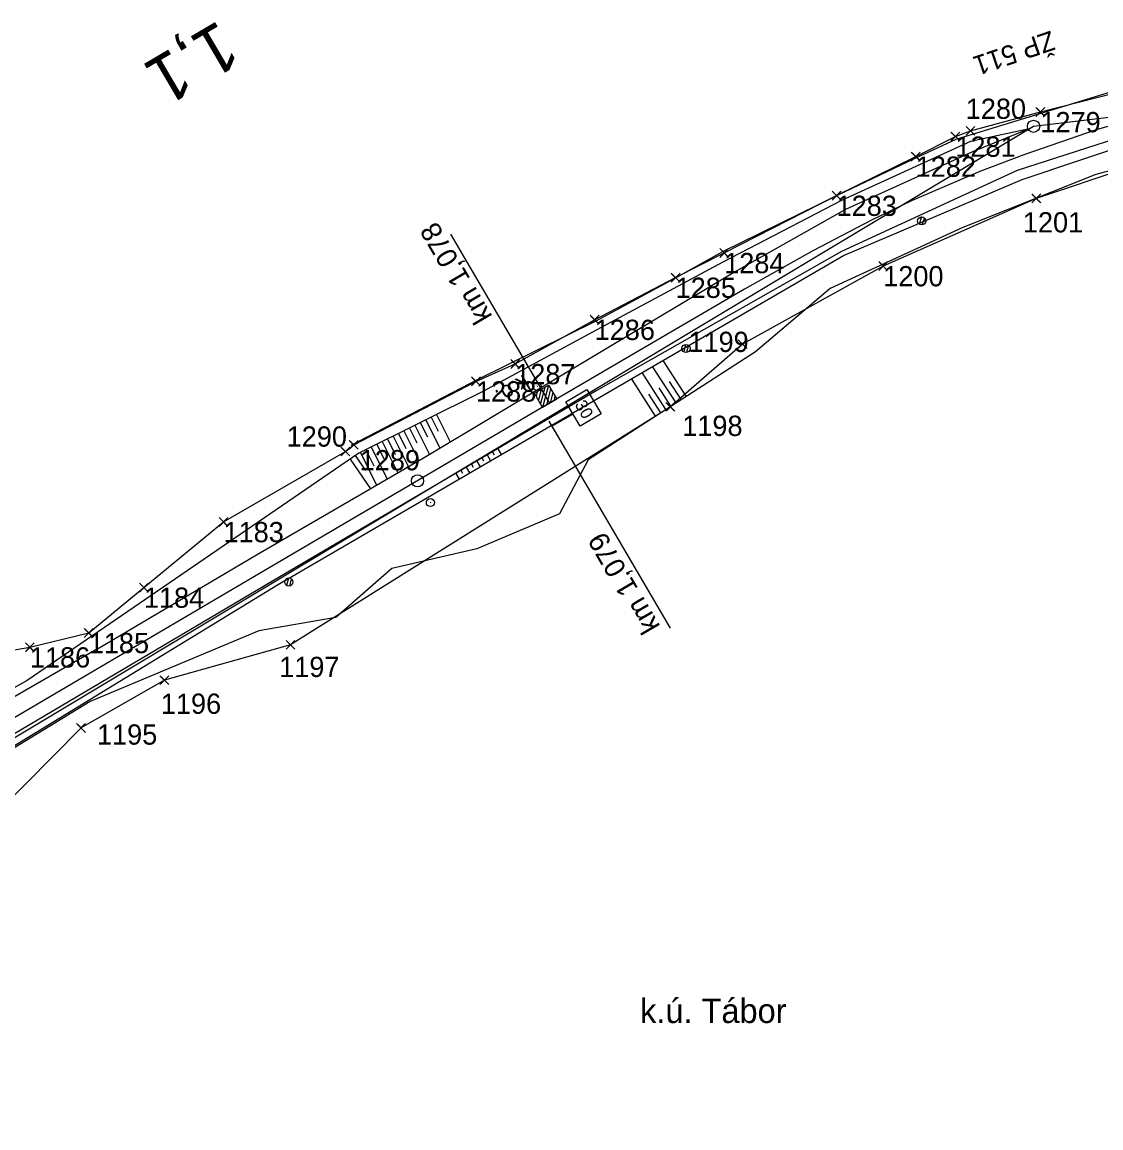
# Model space of a CAD drawing. Extents: x -738085 to -734426, y -1122197 to -1119748.
# Drawn here: x -735102.7 to -734969.6, y -1120290.8 to -1120154.4 of the extents above; entities that cross this region are included whole.
import ezdxf

# ---------------------------------------------------------------- set-up
doc = ezdxf.new("R2010")
doc.units = 0
for name, color, linetype in [('Polygon ku', 7, 'Continuous'), ('SŽDC', 7, 'Continuous'), ('Vrstva 1', 7, 'Continuous'), ('Vrstva 11', 7, 'Continuous'), ('Vrstva 17', 7, 'Continuous'), ('Vrstva 27', 7, 'Continuous'), ('Vrstva 3', 7, 'Continuous'), ('Vrstva 48', 7, 'Continuous'), ('Vrstva 49', 7, 'Continuous'), ('Vrstva 5', 7, 'Continuous'), ('Vrstva 60', 7, 'Continuous'), ('Vrstva 63', 7, 'Continuous'), ('Vrstva 7', 7, 'Continuous')]:
    doc.layers.add(name, color=color, linetype=linetype)

msp = doc.modelspace()

# ---------------------------------------------------------------- linework, layer by layer
at = {"layer": 'SŽDC'}
for p, q in [((-734977.11, -1120165.51), (-734967.74, -1120163.1)), ((-734985.73, -1120167.84), (-734977.11, -1120165.51)), ((-734987.6, -1120168.54), (-734985.73, -1120167.84)), ((-734992.49, -1120171.01), (-734987.6, -1120168.54)), ((-734954.75, -1120168.56), (-734977.62, -1120176.17)), ((-735002.25, -1120175.83), (-734992.49, -1120171.01)), ((-735016.12, -1120182.9), (-735002.25, -1120175.83)), ((-734977.62, -1120176.17), (-734996.5, -1120184.52)), ((-735022.11, -1120185.95), (-735016.12, -1120182.9)), ((-734996.5, -1120184.52), (-735013.84, -1120194.15)), ((-735032.1, -1120191.14), (-735022.11, -1120185.95)), ((-735041.9, -1120196.6), (-735032.1, -1120191.14)), ((-735013.84, -1120194.15), (-735022.76, -1120201.89)), ((-735046.74, -1120198.74), (-735041.9, -1120196.6)), ((-735061.82, -1120206.57), (-735046.74, -1120198.74)), ((-735022.76, -1120201.89), (-735069.62, -1120231.25)), ((-735077.88, -1120216.09), (-735062.84, -1120207.4)), ((-735062.84, -1120207.4), (-735061.82, -1120206.57)), ((-735087.7, -1120224.18), (-735077.88, -1120216.09)), ((-735094.5, -1120229.78), (-735087.7, -1120224.18)), ((-735101.77, -1120231.55), (-735094.5, -1120229.78)), ((-735135.06, -1120237.08), (-735101.77, -1120231.55)), ((-735069.62, -1120231.25), (-735085.17, -1120235.61)), ((-735085.17, -1120235.61), (-735095.46, -1120241.5)), ((-735095.46, -1120241.5), (-735115.98, -1120262.16))]:
    msp.add_line(p, q, dxfattribs=at)
at = {"layer": 'Vrstva 1'}
for points in [[(-734858.48, -1120165.34), (-734868.3, -1120163.18), (-734878.26, -1120161.29), (-734888.48, -1120159.82), (-734893.81, -1120159.28), (-734903.72, -1120158.67), (-734913.62, -1120158.56), (-734922.39, -1120158.89), (-734927.49, -1120159.26), (-734938.14, -1120160.47), (-734948.63, -1120162.22), (-734955.93, -1120163.8), (-734961.26, -1120165.13), (-734970.23, -1120167.73), (-734979.17, -1120170.78), (-734984.57, -1120172.85), (-734992.91, -1120176.44), (-734998.02, -1120178.89), (-735005.2, -1120182.65), (-735013.61, -1120187.35), (-735022.2, -1120192.38), (-735037.65, -1120201.44), (-735048.63, -1120207.9)], [(-734858.48, -1120165.34), (-734868.3, -1120163.18), (-734878.26, -1120161.29), (-734888.48, -1120159.82), (-734893.81, -1120159.28), (-734903.72, -1120158.67), (-734913.62, -1120158.56), (-734922.39, -1120158.89), (-734927.49, -1120159.26), (-734938.14, -1120160.47), (-734948.63, -1120162.22), (-734955.93, -1120163.8), (-734961.26, -1120165.13), (-734970.23, -1120167.73), (-734979.17, -1120170.78), (-734984.57, -1120172.85), (-734992.91, -1120176.44), (-734998.02, -1120178.89), (-735005.2, -1120182.65), (-735013.61, -1120187.35), (-735022.2, -1120192.38), (-735037.65, -1120201.44), (-735048.63, -1120207.9)], [(-735048.63, -1120207.9), (-735071.26, -1120221.19), (-735095.02, -1120235.15), (-735119.18, -1120249.35), (-735123.66, -1120251.99), (-735132.32, -1120257.08), (-735139.95, -1120261.55), (-735146.73, -1120265.54), (-735150.83, -1120267.95), (-735166.13, -1120276.92), (-735184.2, -1120287.53), (-735210.89, -1120303.2), (-735238.62, -1120319.49), (-735239.7, -1120320.12), (-735247.26, -1120324.55), (-735256.8, -1120330.14), (-735273.62, -1120340.02), (-735285.77, -1120347.18), (-735296.08, -1120353.22), (-735304.06, -1120357.75)], [(-735048.63, -1120207.9), (-735071.26, -1120221.19), (-735095.02, -1120235.15), (-735119.18, -1120249.35), (-735123.66, -1120251.99), (-735132.32, -1120257.08), (-735139.95, -1120261.55), (-735146.73, -1120265.54), (-735150.83, -1120267.95), (-735166.13, -1120276.92), (-735184.2, -1120287.53), (-735210.89, -1120303.2), (-735238.62, -1120319.49), (-735239.7, -1120320.12), (-735247.26, -1120324.55), (-735256.8, -1120330.14), (-735273.62, -1120340.02), (-735285.77, -1120347.18), (-735296.08, -1120353.22), (-735304.06, -1120357.75)]]:
    msp.add_lwpolyline(points, dxfattribs=at)
at = {"layer": 'Vrstva 11'}
for p, q in [((-734991.77, -1120178.46), (-734992.08, -1120179.33)), ((-734991.42, -1120178.59), (-734991.72, -1120179.45)), ((-735020.88, -1120194.19), (-735021.11, -1120195.09)), ((-735020.52, -1120194.29), (-735020.75, -1120195.18)), ((-735069.88, -1120223.01), (-735070.12, -1120223.91)), ((-735069.52, -1120223.11), (-735069.75, -1120223.99))]:
    msp.add_line(p, q, dxfattribs=at)
for centre in [(-734991.76, -1120178.95), (-735020.83, -1120194.69), (-735069.83, -1120223.5)]:
    msp.add_circle(centre, 0.5, dxfattribs=at)
at = {"layer": 'Vrstva 17'}
msp.add_lwpolyline([(-734958.83, -1120160.54), (-734967.92, -1120162.89), (-734987.55, -1120168.9), (-734992.59, -1120171.25), (-735002.18, -1120175.82), (-735016.31, -1120182.77), (-735022.02, -1120185.92), (-735031.95, -1120191.31), (-735046.51, -1120198.52), (-735062.17, -1120206.65)], dxfattribs=at)
at = {"layer": 'Vrstva 27'}
msp.add_line((-735039.14, -1120199.33), (-735039.23, -1120199.38), dxfattribs=at)
msp.add_circle((-735039.18, -1120199.36), 0.5, dxfattribs=at)
at = {"layer": 'Vrstva 3'}
for p, q in [((-735049.88, -1120180.59), (-735037.65, -1120201.44)), ((-735037.79, -1120199.21), (-735038.51, -1120201.95)), ((-735039.17, -1120200.02), (-735039.31, -1120200.58)), ((-735038.71, -1120199.75), (-735039.04, -1120201.03)), ((-735038.25, -1120199.48), (-735038.78, -1120201.49)), ((-735037.53, -1120199.67), (-735038.05, -1120201.68)), ((-735037.26, -1120200.13), (-735037.59, -1120201.41)), ((-735036.99, -1120200.58), (-735037.14, -1120201.14))]:
    msp.add_line(p, q, dxfattribs=at)
msp.add_lwpolyline([(-735036.78, -1120200.94), (-735038.51, -1120201.95), (-735039.52, -1120200.22), (-735037.79, -1120199.21)], close=True, dxfattribs=at)
at = {"layer": 'Vrstva 48'}
for p, q in [((-735020.79, -1120200.59), (-735023.65, -1120196.15)), ((-735023.31, -1120202.22), (-735026.25, -1120197.66)), ((-735022.05, -1120201.41), (-735024.95, -1120196.91)), ((-735024.57, -1120203.03), (-735027.55, -1120198.41)), ((-735021.42, -1120201), (-735022.86, -1120198.76)), ((-735023.94, -1120202.63), (-735025.42, -1120200.33)), ((-735022.68, -1120201.81), (-735024.14, -1120199.55)), ((-735052.94, -1120203.5), (-735051.2, -1120206.99)), ((-735052.27, -1120203.16), (-735051.41, -1120204.88)), ((-735051.6, -1120202.83), (-735049.91, -1120206.22)), ((-735055.62, -1120204.83), (-735053.79, -1120208.53)), ((-735054.95, -1120204.5), (-735054.04, -1120206.32)), ((-735054.28, -1120204.16), (-735052.49, -1120207.77)), ((-735053.61, -1120203.83), (-735052.73, -1120205.6)), ((-735058.31, -1120206.17), (-735056.39, -1120210.04)), ((-735057.64, -1120205.83), (-735056.69, -1120207.75)), ((-735056.97, -1120205.5), (-735055.08, -1120209.28)), ((-735056.3, -1120205.17), (-735055.37, -1120207.04)), ((-735061, -1120207.5), (-735058.99, -1120211.55)), ((-735060.33, -1120207.17), (-735059.33, -1120209.17)), ((-735059.65, -1120206.83), (-735057.69, -1120210.79)), ((-735058.98, -1120206.5), (-735058.01, -1120208.46)), ((-735044.71, -1120207.43), (-735044.5, -1120207.79)), ((-735044.06, -1120207.05), (-735043.64, -1120207.78)), ((-735062.25, -1120208.33), (-735059.74, -1120211.99)), ((-735061.63, -1120207.9), (-735060.36, -1120209.76)), ((-735047.29, -1120208.95), (-735047.08, -1120209.31)), ((-735046.65, -1120208.57), (-735046.23, -1120209.29)), ((-735046, -1120208.19), (-735045.79, -1120208.55)), ((-735045.35, -1120207.81), (-735044.93, -1120208.53)), ((-735049.23, -1120210.09), (-735048.82, -1120210.8)), ((-735048.59, -1120209.71), (-735048.38, -1120210.07)), ((-735047.94, -1120209.33), (-735047.52, -1120210.04))]:
    msp.add_line(p, q, dxfattribs=at)
at = {"layer": 'Vrstva 49'}
for p, q in [((-734978.67, -1120167.61), (-734985.73, -1120169.16)), ((-734965.26, -1120167.97), (-734979.99, -1120172.75)), ((-734985.73, -1120169.16), (-735001.65, -1120176.44)), ((-734953.78, -1120168.78), (-734970.28, -1120173.21)), ((-734979.99, -1120172.75), (-735001.65, -1120182.71)), ((-734970.28, -1120173.21), (-734986.68, -1120179.78)), ((-735001.65, -1120176.44), (-735016.28, -1120184.05)), ((-734986.68, -1120179.78), (-735003.03, -1120187.3)), ((-735001.65, -1120182.71), (-735031.91, -1120199.9)), ((-735016.28, -1120184.05), (-735031.84, -1120192.39)), ((-735003.03, -1120187.3), (-735012.25, -1120195.08)), ((-735031.84, -1120192.39), (-735045.79, -1120199.94)), ((-735012.25, -1120195.08), (-735032.89, -1120208.41)), ((-735031.91, -1120199.9), (-735071.62, -1120223.27)), ((-735045.79, -1120199.94), (-735061.17, -1120207.59)), ((-735061.17, -1120207.59), (-735102.12, -1120235.63)), ((-735032.89, -1120208.41), (-735036.45, -1120215.1)), ((-735036.45, -1120215.1), (-735046.62, -1120219.42)), ((-735046.62, -1120219.42), (-735057.12, -1120221.84)), ((-735057.12, -1120221.84), (-735064.02, -1120227.89)), ((-735071.62, -1120223.27), (-735122.8, -1120253.54)), ((-735064.02, -1120227.89), (-735073.54, -1120229.51)), ((-735073.54, -1120229.51), (-735094.31, -1120238.23)), ((-735094.31, -1120238.23), (-735118.4, -1120252.93))]:
    msp.add_line(p, q, dxfattribs=at)
for points in [[(-735120.53, -1120253.93), (-735071.24, -1120223.86), (-735031.45, -1120200.68), (-735001.39, -1120183.23), (-734979.37, -1120173.86), (-734964.99, -1120169.04), (-734946.77, -1120164.63), (-734926.51, -1120162.42), (-734904.58, -1120162.2), (-734885.6, -1120163.73), (-734860.45, -1120168.24), (-734808.17, -1120179.8), (-734802.31, -1120181.01), (-734795.9, -1120182.78), (-734795.12, -1120182.96), (-734773.64, -1120187.62), (-734748.07, -1120193.22), (-734734.64, -1120197.94), (-734724.28, -1120200.04), (-734701.99, -1120203.61), (-734701.41, -1120203.78)], [(-735093.44, -1120231.75), (-735073.83, -1120220.15), (-735052.91, -1120208.02), (-735030.69, -1120194.68), (-735015.24, -1120185.47), (-735001.11, -1120177.49), (-734985.43, -1120170.39), (-734978.67, -1120167.61)], [(-735093.44, -1120231.75), (-735123.16, -1120248.87), (-735124.89, -1120249.94)], [(-735102.12, -1120235.63), (-735123.55, -1120247.66), (-735124.89, -1120249.94)]]:
    msp.add_lwpolyline(points, dxfattribs=at)
at = {"layer": 'Vrstva 5'}
for p, q in [((-735037.37, -1120204.29), (-735034.78, -1120202.77)), ((-735037.75, -1120203.64), (-735036.99, -1120204.94)), ((-735037.37, -1120204.29), (-735022.77, -1120229.21))]:
    msp.add_line(p, q, dxfattribs=at)
msp.add_lwpolyline([(-735033.9, -1120204.28), (-735035.67, -1120201.26), (-735033.08, -1120199.74), (-735031.31, -1120202.76)], close=True, dxfattribs=at)
at = {"layer": 'Vrstva 60'}
for p, q in [((-734976.66, -1120165.96), (-734977.66, -1120164.96)), ((-734976.66, -1120165.06), (-734977.66, -1120166.06)), ((-734977.56, -1120165.96), (-734976.56, -1120164.96)), ((-734977.56, -1120165.06), (-734976.56, -1120166.06)), ((-734977.11, -1120165.51), (-734977.11, -1120165.51)), ((-734987.15, -1120168.99), (-734988.15, -1120167.99)), ((-734988.05, -1120168.99), (-734987.05, -1120167.99)), ((-734985.28, -1120168.29), (-734986.28, -1120167.29)), ((-734985.28, -1120167.39), (-734986.28, -1120168.39)), ((-734986.18, -1120168.29), (-734985.18, -1120167.29)), ((-734986.18, -1120167.39), (-734985.18, -1120168.39)), ((-734985.73, -1120167.84), (-734985.73, -1120167.84)), ((-734987.15, -1120168.09), (-734988.15, -1120169.09)), ((-734988.05, -1120168.09), (-734987.05, -1120169.09)), ((-734987.6, -1120168.54), (-734987.6, -1120168.54)), ((-734992.04, -1120171.46), (-734993.04, -1120170.46)), ((-734992.04, -1120170.56), (-734993.04, -1120171.56)), ((-734992.94, -1120171.46), (-734991.94, -1120170.46)), ((-734992.94, -1120170.56), (-734991.94, -1120171.56)), ((-734992.49, -1120171.01), (-734992.49, -1120171.01)), ((-735001.8, -1120176.28), (-735002.8, -1120175.28)), ((-735001.8, -1120175.38), (-735002.8, -1120176.38)), ((-735002.7, -1120176.28), (-735001.7, -1120175.28)), ((-735002.7, -1120175.38), (-735001.7, -1120176.38)), ((-735002.25, -1120175.83), (-735002.25, -1120175.83)), ((-734977.17, -1120176.62), (-734978.17, -1120175.62)), ((-734977.17, -1120175.72), (-734978.17, -1120176.72)), ((-734978.07, -1120176.62), (-734977.07, -1120175.62)), ((-734978.07, -1120175.72), (-734977.07, -1120176.72)), ((-734977.62, -1120176.17), (-734977.62, -1120176.17)), ((-735015.67, -1120183.35), (-735016.67, -1120182.35)), ((-735015.67, -1120182.45), (-735016.67, -1120183.45)), ((-735016.57, -1120183.35), (-735015.57, -1120182.35)), ((-735016.57, -1120182.45), (-735015.57, -1120183.45)), ((-735016.12, -1120182.9), (-735016.12, -1120182.9)), ((-734996.05, -1120184.97), (-734997.05, -1120183.97)), ((-734996.05, -1120184.07), (-734997.05, -1120185.07)), ((-734996.95, -1120184.97), (-734995.95, -1120183.97)), ((-734996.95, -1120184.07), (-734995.95, -1120185.07)), ((-735021.66, -1120186.4), (-735022.66, -1120185.4)), ((-735021.66, -1120185.5), (-735022.66, -1120186.5)), ((-735022.56, -1120186.4), (-735021.56, -1120185.4)), ((-735022.56, -1120185.5), (-735021.56, -1120186.5)), ((-734996.5, -1120184.52), (-734996.5, -1120184.52)), ((-735022.11, -1120185.95), (-735022.11, -1120185.95)), ((-735031.65, -1120191.59), (-735032.65, -1120190.59)), ((-735031.65, -1120190.69), (-735032.65, -1120191.69)), ((-735032.55, -1120191.59), (-735031.55, -1120190.59)), ((-735032.55, -1120190.69), (-735031.55, -1120191.69)), ((-735032.1, -1120191.14), (-735032.1, -1120191.14)), ((-735013.39, -1120194.6), (-735014.39, -1120193.6)), ((-735013.39, -1120193.7), (-735014.39, -1120194.7)), ((-735014.29, -1120194.6), (-735013.29, -1120193.6)), ((-735014.29, -1120193.7), (-735013.29, -1120194.7)), ((-735013.84, -1120194.15), (-735013.84, -1120194.15)), ((-735041.45, -1120197.05), (-735042.45, -1120196.05)), ((-735041.45, -1120196.15), (-735042.45, -1120197.15)), ((-735042.35, -1120197.05), (-735041.35, -1120196.05)), ((-735042.35, -1120196.15), (-735041.35, -1120197.15)), ((-735041.9, -1120196.6), (-735041.9, -1120196.6)), ((-735046.29, -1120199.19), (-735047.29, -1120198.19)), ((-735046.29, -1120198.29), (-735047.29, -1120199.29)), ((-735047.19, -1120199.19), (-735046.19, -1120198.19)), ((-735047.19, -1120198.29), (-735046.19, -1120199.29)), ((-735046.74, -1120198.74), (-735046.74, -1120198.74)), ((-735022.31, -1120202.34), (-735023.31, -1120201.34)), ((-735022.31, -1120201.44), (-735023.31, -1120202.44)), ((-735023.21, -1120202.34), (-735022.21, -1120201.34)), ((-735023.21, -1120201.44), (-735022.21, -1120202.44)), ((-735022.76, -1120201.89), (-735022.76, -1120201.89)), ((-735061.37, -1120207.02), (-735062.37, -1120206.02)), ((-735061.37, -1120206.12), (-735062.37, -1120207.12)), ((-735062.27, -1120207.02), (-735061.27, -1120206.02)), ((-735062.27, -1120206.12), (-735061.27, -1120207.12)), ((-735062.39, -1120207.85), (-735063.39, -1120206.85)), ((-735062.39, -1120206.95), (-735063.39, -1120207.95)), ((-735063.29, -1120207.85), (-735062.29, -1120206.85)), ((-735063.29, -1120206.95), (-735062.29, -1120207.95)), ((-735062.84, -1120207.4), (-735062.84, -1120207.4)), ((-735061.82, -1120206.57), (-735061.82, -1120206.57)), ((-735077.43, -1120216.54), (-735078.43, -1120215.54)), ((-735077.43, -1120215.64), (-735078.43, -1120216.64)), ((-735078.33, -1120216.54), (-735077.33, -1120215.54)), ((-735078.33, -1120215.64), (-735077.33, -1120216.64)), ((-735077.88, -1120216.09), (-735077.88, -1120216.09)), ((-735087.25, -1120224.63), (-735088.25, -1120223.63)), ((-735087.25, -1120223.73), (-735088.25, -1120224.73)), ((-735088.15, -1120224.63), (-735087.15, -1120223.63)), ((-735088.15, -1120223.73), (-735087.15, -1120224.73)), ((-735087.7, -1120224.18), (-735087.7, -1120224.18)), ((-735094.05, -1120230.23), (-735095.05, -1120229.23)), ((-735094.05, -1120229.33), (-735095.05, -1120230.33)), ((-735094.95, -1120230.23), (-735093.95, -1120229.23)), ((-735094.95, -1120229.33), (-735093.95, -1120230.33)), ((-735094.5, -1120229.78), (-735094.5, -1120229.78)), ((-735069.17, -1120231.7), (-735070.17, -1120230.7)), ((-735070.07, -1120231.7), (-735069.07, -1120230.7)), ((-735101.32, -1120232), (-735102.32, -1120231)), ((-735101.32, -1120231.1), (-735102.32, -1120232.1)), ((-735102.22, -1120232), (-735101.22, -1120231)), ((-735102.22, -1120231.1), (-735101.22, -1120232.1)), ((-735101.77, -1120231.55), (-735101.77, -1120231.55)), ((-735069.17, -1120230.8), (-735070.17, -1120231.8)), ((-735070.07, -1120230.8), (-735069.07, -1120231.8)), ((-735069.62, -1120231.25), (-735069.62, -1120231.25)), ((-735084.72, -1120236.06), (-735085.72, -1120235.06)), ((-735084.72, -1120235.16), (-735085.72, -1120236.16)), ((-735085.62, -1120236.06), (-735084.62, -1120235.06)), ((-735085.62, -1120235.16), (-735084.62, -1120236.16)), ((-735085.17, -1120235.61), (-735085.17, -1120235.61)), ((-735095.01, -1120241.95), (-735096.01, -1120240.95)), ((-735095.01, -1120241.05), (-735096.01, -1120242.05)), ((-735095.91, -1120241.95), (-735094.91, -1120240.95)), ((-735095.91, -1120241.05), (-735094.91, -1120242.05)), ((-735095.46, -1120241.5), (-735095.46, -1120241.5))]:
    msp.add_line(p, q, dxfattribs=at)
at = {"layer": 'Vrstva 63'}
for p, q in [((-734977.95, -1120167.28), (-734893.88, -1120157.02)), ((-735121.84, -1120253.57), (-734977.95, -1120167.28)), ((-734977.9, -1120167.26), (-734978, -1120167.3))]:
    msp.add_line(p, q, dxfattribs=at)
msp.add_circle((-734977.95, -1120167.28), 0.756, dxfattribs=at)
at = {"layer": 'Vrstva 7'}
msp.add_line((-735052.31, -1120213.67), (-735052.4, -1120213.72), dxfattribs=at)
for centre, radius in [((-735053.94, -1120211.01), 0.75), ((-735053.94, -1120211.01), 0.75), ((-735052.36, -1120213.7), 0.5)]:
    msp.add_circle(centre, radius, dxfattribs=at)

# ---------------------------------------------------------------- texts
at = {"layer": 'Polygon ku'}
msp.add_text('k.ú. Tábor', height=3, dxfattribs=at).set_placement((-735026.49, -1120277.9))
at = {"layer": 'Vrstva 27'}
msp.add_text('k.o.', height=2, rotation=210.4052, dxfattribs=at).set_placement((-735040.85, -1120197.83))
at = {"layer": 'Vrstva 3'}
msp.add_text('km 1,078', height=2.5, rotation=120.4052, dxfattribs=at).set_placement((-735044.65, -1120190.74))
at = {"layer": 'Vrstva 5'}
for s, height, rotation, p in [('30', 1.5, 300.4377, (-735034.6, -1120201.6)), ('km 1,079', 2.5, 120.3686, (-735023.94, -1120228.97))]:
    msp.add_text(s, height=height, rotation=rotation, dxfattribs=at).set_placement(p)
at = {"layer": 'Vrstva 60'}
for s, p in [('1280', (-734986.32, -1120166.36)), ('1279', (-734977.11, -1120168.01)), ('1281', (-734987.6, -1120171.04)), ('1282', (-734992.49, -1120173.51)), ('1283', (-735002.25, -1120178.33)), ('1201', (-734979.27, -1120180.37)), ('1284', (-735016.12, -1120185.4)), ('1200', (-734996.5, -1120187.02)), ('1285', (-735022.11, -1120188.45)), ('1286', (-735032.1, -1120193.64)), ('1199', (-735020.53, -1120195.12)), ('1287', (-735041.9, -1120199.1)), ('1288', (-735046.74, -1120201.24)), ('1198', (-735021.29, -1120205.48)), ('1290', (-735070.09, -1120206.8)), ('1289', (-735061.08, -1120209.72)), ('1183', (-735077.88, -1120218.59)), ('1184', (-735087.7, -1120226.68)), ('1185', (-735094.5, -1120232.28)), ('1186', (-735101.77, -1120234.05)), ('1197', (-735071.01, -1120235.22)), ('1196', (-735085.61, -1120239.76)), ('1195', (-735093.49, -1120243.56))]:
    msp.add_text(s, height=2.5, dxfattribs=at).set_placement(p)
at = {"layer": 'Vrstva 63'}
msp.add_text('ŽP 511', height=2.4, rotation=198.8246, dxfattribs=at).set_placement((-734975.81, -1120155.45))
at = {"layer": 'Vrstva 7'}
msp.add_text('1,1', height=6, rotation=210.44, dxfattribs=at).set_placement((-735078.4, -1120154.11))
msp.add_text('1,1', height=6, rotation=210.44, dxfattribs=at).set_placement((-735078.4, -1120154.11))

doc.saveas('drawing.dxf')
